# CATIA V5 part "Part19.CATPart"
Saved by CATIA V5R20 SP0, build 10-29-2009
Part number: 9SA160016-T
Revision: ANY
Definition: UNKNOWN
Nomenclature: 9SA160016-T
Source: Unknown
Bounding box of the stored display mesh (mm): x -5.85 to 5.85, y 0 to 5.95, z -6 to 6
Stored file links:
  C:\Users\Utente\Desktop\IO LAVORO\3D X SITO CF\CUMSA\3D files SA\SA 160416\Part19.CATPart
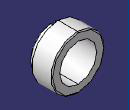
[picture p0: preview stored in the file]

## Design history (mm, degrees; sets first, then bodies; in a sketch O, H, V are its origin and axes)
Body1 "Chaflán1" (main body)
  Solid1: solid without history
